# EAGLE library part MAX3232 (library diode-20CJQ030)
max3232CD or max3232ID digikey parts: 296-13094-1-ND and 296-13098-1-ND respectively ~$2.60 (both 16pin soic narrow, but with different temperature grades) Texas Instruments 3V to 5.5V 250kbit multichannel RS-232 line driver/receiver with +-15kV ESD protection available as TI samples and digikey carries them as well, available in SOIC16 narrow/wide package and TSSOP as well. pin compatible with maxim-ic max232 and max3232 parts
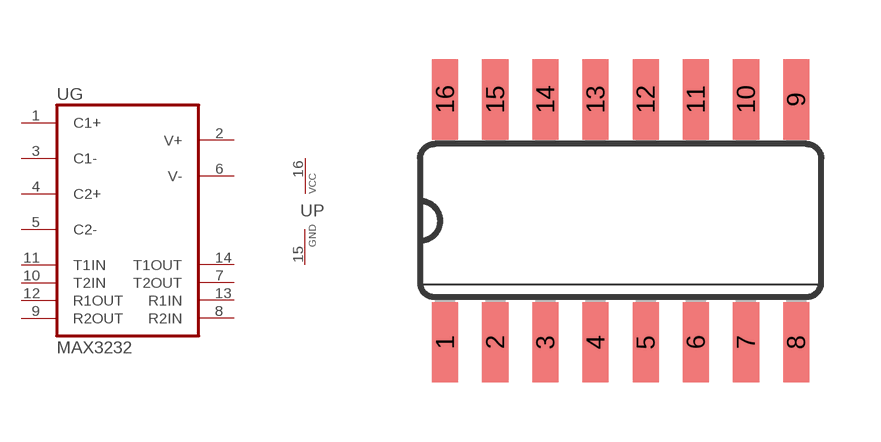
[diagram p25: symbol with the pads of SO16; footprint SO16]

Designator prefix U; gates G=MAX232 P=VCC-GND

## MAX3232S  [SO16]
1  G:C1+
2  G:V+
3  G:C1-
4  G:C2+
5  G:C2-
6  G:V-
7  G:T2OUT  out
8  G:R2IN  in
9  G:R2OUT  out
10  G:T2IN  in
11  G:T1IN  in
12  G:R1OUT  out
13  G:R1IN  in
14  G:T1OUT  out
15  P:GND  pwr
16  P:VCC  pwr

## Footprint SO16 (pad centres in mm)
Small Outline Package
smd 0.66 x 2.032: 1 -4.445,-3.073; 2 -3.175,-3.073; 3 -1.905,-3.073; 4 -0.635,-3.073; 5 0.635,-3.073; 6 1.905,-3.073; 7 3.175,-3.073; 8 4.445,-3.073; 9 4.445,3.073; 10 3.175,3.073; 11 1.905,3.073; 12 0.635,3.073; 13 -0.635,3.073; 14 -1.905,3.073; 15 -3.175,3.073; 16 -4.445,3.073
